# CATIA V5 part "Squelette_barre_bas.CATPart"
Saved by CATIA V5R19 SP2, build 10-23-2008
Part number: squelette_barre_bas
Bounding box of the stored display mesh (mm): x -40 to 40, y -770 to -294, z -140 to -48
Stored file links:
  C:\Users\Pauline\Desktop\CFAO_Catia\Compte_rendu\pmayet_assemblage_animation4\Squelette_barre_bas.CATPart
  C:\Users\Pauline\Desktop\CFAO_Catia\Compte_rendu\pmayet_assemblage_animation4\pmayet_assemblage_animation.CATProduct
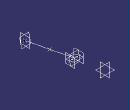
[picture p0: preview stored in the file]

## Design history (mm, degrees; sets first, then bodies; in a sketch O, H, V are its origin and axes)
Set1
  Point1 to Point3: linked copy from another document
Set2
  Point4: type Between, FirstPoint Point1, SecondPoint Point2, Ratio 0.5
  Line1: type PtPt, FirstPoint Point1, SecondPoint Point2
  Line2: type PtPt, FirstPoint Point3, SecondPoint Point4
  Plane1: type 2Lines, Element1 Line1, Element2 Line2
  Plane2: type Normal, Curve Line2, RefPoint Point4
  Plane3: type Normal, Curve Line2, RefPoint Point3
  Point5: type Between, FirstPoint Point3, SecondPoint Point4, Ratio 0.5
  Plane4: type Normal, Curve Line1, RefPoint Point3
  Plane5: type Normal, Curve Line1, RefPoint Point1
  Plane6: type Normal, Curve Line1, RefPoint Point2
Body1 (main body)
